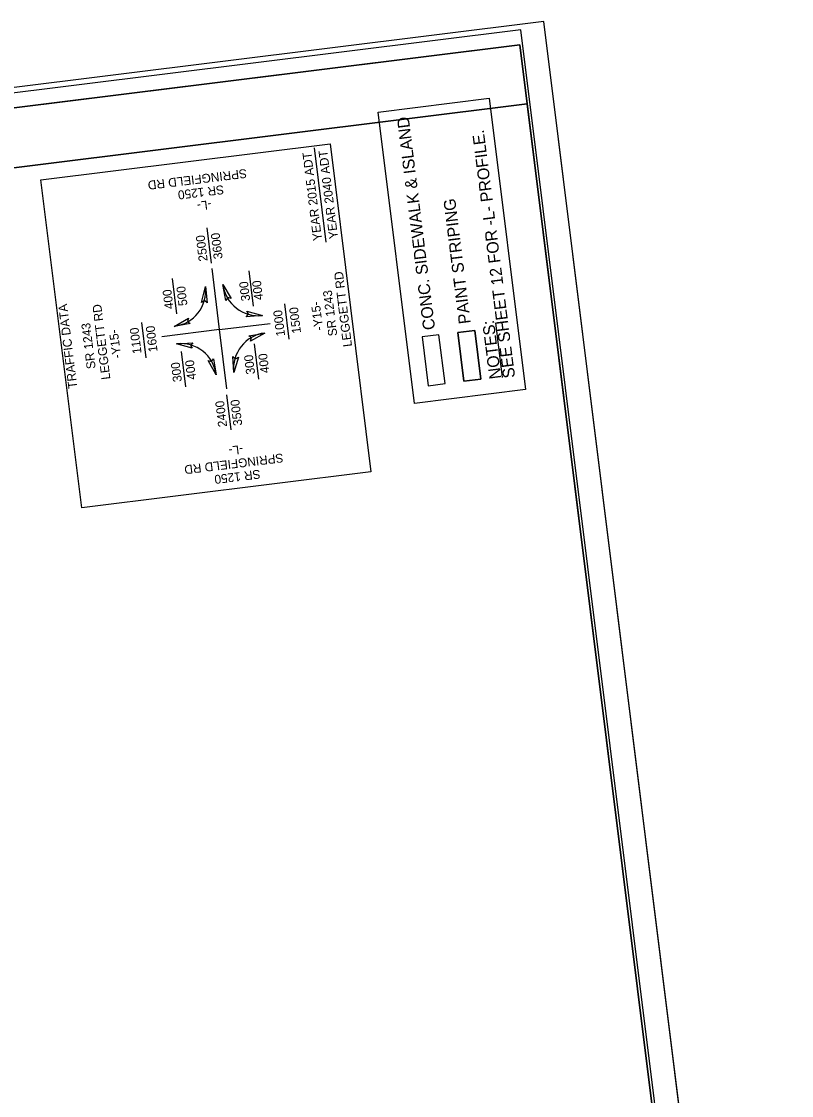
# Model space of a CAD drawing. Extents: x 2367685 to 2368979, y 807242 to 809048.
# Drawn here: x 2368332 to 2368979, y 808145 to 809048 of the extents above; entities that cross this region are included whole.
import ezdxf

# ---------------------------------------------------------------- set-up
doc = ezdxf.new("R2010")
doc.units = 0
for name, color, linetype in [('Old_Level_10', 7, 'Continuous'), ('Old_Level_14', 7, 'Continuous'), ('Old_Level_15', 7, 'Continuous'), ('Old_Level_2', 7, 'Continuous'), ('Old_Level_22', 7, 'Continuous'), ('Old_Level_3', 7, 'Continuous'), ('Old_Level_4', 7, 'Continuous'), ('Old_Level_5', 7, 'Continuous'), ('Old_Level_6', 7, 'Continuous'), ('Old_Level_7', 7, 'Continuous'), ('Plot Label CELL', 7, 'Continuous'), ('Plot Shape CELL', 7, 'Continuous')]:
    doc.layers.add(name, color=color, linetype=linetype)

msp = doc.modelspace()

# ---------------------------------------------------------------- linework, layer by layer
at = {"layer": 'Old_Level_10'}
msp.add_lwpolyline([(2367894.53, 807409.74), (2368936.44, 807539.65), (2368750.87, 809028.13), (2367918.8, 808924.4), (2367948.4, 808686.99), (2367738.54, 808660.82)], close=True, dxfattribs=at)
at = {"layer": 'Old_Level_14'}
msp.add_lwpolyline([(2368688.06, 808743.33), (2368682.94, 808784.33), (2368668.78, 808782.57), (2368673.89, 808741.56), (2368688.06, 808743.33)], dxfattribs=at)
at = {"layer": 'Old_Level_15'}
msp.add_line((2368979.38, 807377.23), (2368771.11, 809047.8), dxfattribs=at)
at = {"layer": 'Old_Level_2'}
msp.add_lwpolyline([(2368930.25, 807589.27), (2368757.06, 808978.53), (2367924.99, 808874.8), (2367948.4, 808686.99), (2367738.54, 808660.82), (2367888.32, 807459.37)], close=True, dxfattribs=at)
at = {"layer": 'Old_Level_22'}
msp.add_lwpolyline([(2368826.65, 807671.15), (2368834.5, 807611.56), (2368735.93, 807593.18), (2368175.69, 807520.89), (2367878.85, 807535.48), (2367738.54, 808660.82), (2367948.4, 808686.99), (2367924.99, 808874.8), (2368757.06, 808978.53), (2368918.62, 807682.61)], close=True, dxfattribs=at)
msp.add_lwpolyline([(2368826.65, 807671.15), (2368834.5, 807611.56), (2368735.93, 807593.18), (2368175.69, 807520.89), (2367878.85, 807535.48), (2367738.54, 808660.82), (2367948.4, 808686.99), (2367924.99, 808874.8), (2368757.06, 808978.53), (2368918.62, 807682.61)], close=True, dxfattribs=at)
at = {"layer": 'Old_Level_3'}
for points in [[(2368483.38, 808811.6), (2368486.53, 808824.87), (2368488.07, 808811.23), (2368485.79, 808813.09)], [(2368503.82, 808813.27), (2368501.36, 808826.7), (2368508.26, 808814.83), (2368505.43, 808815.62)], [(2368521.48, 808804.18), (2368534.67, 808800.68), (2368520.99, 808799.49), (2368522.91, 808801.72)], [(2368473.81, 808793.88), (2368460.39, 808791.41), (2368472.25, 808798.33), (2368471.46, 808795.49)], [(2368523.03, 808783.61), (2368536.49, 808785.85), (2368524.51, 808779.14), (2368525.34, 808781.97)], [(2368475.46, 808773.01), (2368462.34, 808776.73), (2368476.04, 808777.68), (2368474.07, 808775.48)], [(2368493.47, 808764.19), (2368495.64, 808750.72), (2368488.99, 808762.73), (2368491.81, 808761.88)], [(2368514.39, 808765.61), (2368510.47, 808752.54), (2368509.73, 808766.25), (2368511.89, 808764.26)]]:
    msp.add_lwpolyline(points, close=True, dxfattribs=at)
at = {"layer": 'Old_Level_4'}
msp.add_lwpolyline([(2368957.92, 807387.66), (2368751.81, 809040.84), (2367704.92, 808910.34), (2367911.03, 807257.14)], close=True, dxfattribs=at)
at = {"layer": 'Old_Level_5'}
msp.add_lwpolyline([(2368703.94, 808745.31), (2368698.82, 808786.31), (2368712.99, 808788.08), (2368718.1, 808747.07)], close=True, dxfattribs=at)
for points in [[(2368718.1, 808747.07), (2368712.99, 808788.08), (2368698.82, 808786.31), (2368703.94, 808745.31), (2368718.1, 808747.07)], [(2368688.06, 808743.33), (2368682.94, 808784.33), (2368668.78, 808782.57), (2368673.89, 808741.56), (2368688.06, 808743.33)]]:
    msp.add_lwpolyline(points, dxfattribs=at)
at = {"layer": 'Old_Level_6'}
msp.add_lwpolyline([(2368979.38, 807377.23), (2368771.11, 809047.8), (2367684.52, 808912.34), (2367892.79, 807241.77)], close=True, dxfattribs=at)
at = {"layer": 'Old_Level_7'}
for p, q in [((2368588.17, 808862.21), (2368578.41, 808941.62)), ((2368491.85, 808844.53), (2368488.2, 808874.19)), ((2368498.5, 808788.71), (2368492.17, 808840.2)), ((2368462.46, 808802.13), (2368458.81, 808831.79)), ((2368527.15, 808808.43), (2368523.5, 808838.09)), ((2368557.07, 808780.63), (2368553.42, 808810.29)), ((2368436.88, 808765.06), (2368433.24, 808794.72)), ((2368498.5, 808788.71), (2368450.07, 808782.75)), ((2368498.5, 808788.71), (2368541.04, 808793.94)), ((2368504.63, 808738.84), (2368498.5, 808788.71)), ((2368531.6, 808747.16), (2368527.95, 808776.82)), ((2368470.15, 808740.56), (2368466.5, 808770.22)), ((2368508.31, 808704.35), (2368504.67, 808734.02))]:
    msp.add_line(p, q, dxfattribs=at)
msp.add_lwpolyline([(2368625.72, 808669.28), (2368382.6, 808638.97), (2368348.24, 808914.54), (2368591.37, 808944.85)], close=True, dxfattribs=at)
for centre, start, end in [((2368456.87, 808821.23), 277.00761, 7.00761), ((2368531.02, 808830.34), 187.00761, 277.00761), ((2368540.14, 808756.19), 97.00761, 187.00761), ((2368465.98, 808747.07), 7.00761, 97.00761)]:
    msp.add_arc(centre, 29.89, start, end, dxfattribs=at)
at = {"layer": 'Plot Label CELL'}
msp.add_line((2368736.5, 808748.36), (2368730.65, 808794.48), dxfattribs=at)
msp.add_lwpolyline([(2368662.44, 808726.7), (2368631.91, 808971.62), (2368725.08, 808983.24), (2368755.61, 808738.32)], close=True, dxfattribs=at)
at = {"layer": 'Plot Shape CELL'}
for points in [[(2367708.94, 808898.27), (2367894.51, 807409.76), (2368936.44, 807539.65), (2368750.87, 809028.14)], [(2368936.44, 807539.65), (2367894.53, 807409.74), (2367733.67, 808699.73), (2367882.58, 808718.31), (2367857.85, 808916.81), (2368750.87, 809028.14)]]:
    msp.add_lwpolyline(points, close=True, dxfattribs=at)

# ---------------------------------------------------------------- texts
at = {"layer": 'Old_Level_7'}
for s, height, rotation, p in [('YEAR 2015 ADT', 7.4713, 97.00761, (2368584.68, 808863.91)), ('YEAR 2040 ADT', 7.4713, 97.00761, (2368598.18, 808865.48)), ('SPRINGFIELD RD', 7.4713, 187.00761, (2368520.96, 808923.89)), ('SR 1250', 7.471, 187.00761, (2368501.68, 808910.23)), ('-L-', 7.471, 187.00761, (2368491.24, 808897.66)), ('2500', 7.471, 97.00761, (2368488.52, 808846.53)), ('3600', 7.471, 97.00761, (2368501.17, 808848.49)), ('LEGGETT RD', 7.471, 97.00761, (2368609.89, 808774.69)), ('400', 7.471, 97.00761, (2368459.9, 808806.4)), ('500', 7.471, 97.00761, (2368471.51, 808809.14)), ('300', 7.471, 97.00761, (2368524.29, 808813.12)), ('400', 7.471, 97.00761, (2368535.18, 808813.95)), ('SR 1243', 7.471, 97.00761, (2368597.49, 808783.67)), ('TRAFFIC DATA', 7.4713, 97.00761, (2368378.92, 808739.62)), ('LEGGETT RD', 7.471, 97.00761, (2368406.73, 808747.15)), ('1000', 7.471, 97.00761, (2368553.63, 808783.53)), ('1500', 7.471, 97.00761, (2368567.02, 808785.98)), ('-Y15-', 7.471, 97.00761, (2368585.62, 808788.37)), ('SR 1243', 7.471, 97.00761, (2368394.33, 808756.13)), ('-Y15-', 7.471, 97.00761, (2368415.83, 808764.94)), ('1100', 7.471, 97.00761, (2368432.94, 808768.79)), ('1600', 7.471, 97.00761, (2368446.44, 808770.35)), ('400', 7.471, 97.00761, (2368540.39, 808752.58)), ('300', 7.471, 97.00761, (2368466.9, 808745.18)), ('400', 7.471, 97.00761, (2368478.81, 808747.07)), ('300', 7.471, 97.00761, (2368528.39, 808751.46)), ('2400', 7.471, 97.00761, (2368504.87, 808707.29)), ('3500', 7.471, 97.00761, (2368517.63, 808708.32)), ('-L-', 7.471, 187.00761, (2368517.83, 808691.83)), ('SPRINGFIELD RD', 7.4713, 187.00761, (2368551.64, 808684.7)), ('SR 1250', 7.471, 187.00761, (2368532.37, 808671.04))]:
    msp.add_text(s, height=height, rotation=rotation, dxfattribs=at).set_placement(p)
at = {"layer": 'Plot Label CELL'}
for s, rotation, p in [('CONC. SIDEWALK & ISLAND', 97.10772, (2368679.81, 808789.03)), ('SEE SHEET 12 FOR -L- PROFILE.', 97.22897, (2368747.04, 808748.55)), ('PAINT STRIPING', 97.10772, (2368709.68, 808794.11)), ('NOTES:', 97.22897, (2368735.38, 808747.74))]:
    msp.add_text(s, height=10, rotation=rotation, dxfattribs=at).set_placement(p)

doc.saveas('drawing.dxf')
